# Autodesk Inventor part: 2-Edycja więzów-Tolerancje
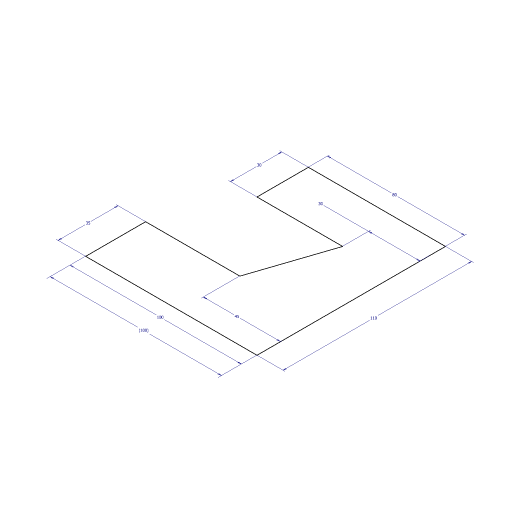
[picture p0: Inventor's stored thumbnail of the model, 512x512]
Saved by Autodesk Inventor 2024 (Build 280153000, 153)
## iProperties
Company: ATC
Shininess: 20.0
Length Units: 11269
Angle Units: 11279
Time Units: 11290
Mass Units: 11283
Compacted: True
Created: 2023-03
Part Number: 2-Edycja więzów-Tolerancje
Document SubType Name: Modeling
Designer: Andrzej Jaskulski
Material: Kurs-AJ
Density: 1 g/cm^3
Appearance: Kurs-AJ
Checked By: A.J.
Engr Approved By: Andrzej Jaskulski
Mfg Approved By: Andrzej Jaskulski
Authority: A.J.
Density: 0.0
Volumn: 0.0
Area: 0.0
PropertySet Name: Model Information
Control State: 0
Master: False
Checked Out: False
Title: A.J.: Kurs R2024-MEP
Author: Andrzej Jaskulski
Revision Number: 1/24
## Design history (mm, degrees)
sketch "Ceownik"
  geometry: L1 (-25.738, 9.563)-(74.262, 9.563); L2 (74.262, 9.563)-(74.262, 119.563); L3 (74.262, 119.563)-(-5.738, 119.563); L4 (-5.738, 119.563)-(-5.738, 89.563); L5 (-5.738, 89.563)-(44.262, 89.563); L6 (44.262, 89.563)-(29.262, 44.563); L7 (29.262, 44.563)-(-25.738, 44.563); L8 (-25.738, 44.563)-(-25.738, 9.563)
  constraints: 16 end point, 4 horizontal, 3 vertical, 1 other
  dimensions: "d1" = 100 distance of L1.start L1.end; "d2" = 110 distance of L1.end L2.end; "d3" = 80 distance of L2.end L3.end; "d4" = 30 distance of L3.end L4.end; "d5" = 35 distance of L7.end L1.start; "d6" = 45 distance from line of L2 L6.end; "d7" = 30 distance from line of L2 L5.end; "AK" = 100 distance between parallel lines of L2 L8 (derived)
node "Korpusy bryłowe"
node "Korpusy powierzchniowe"
